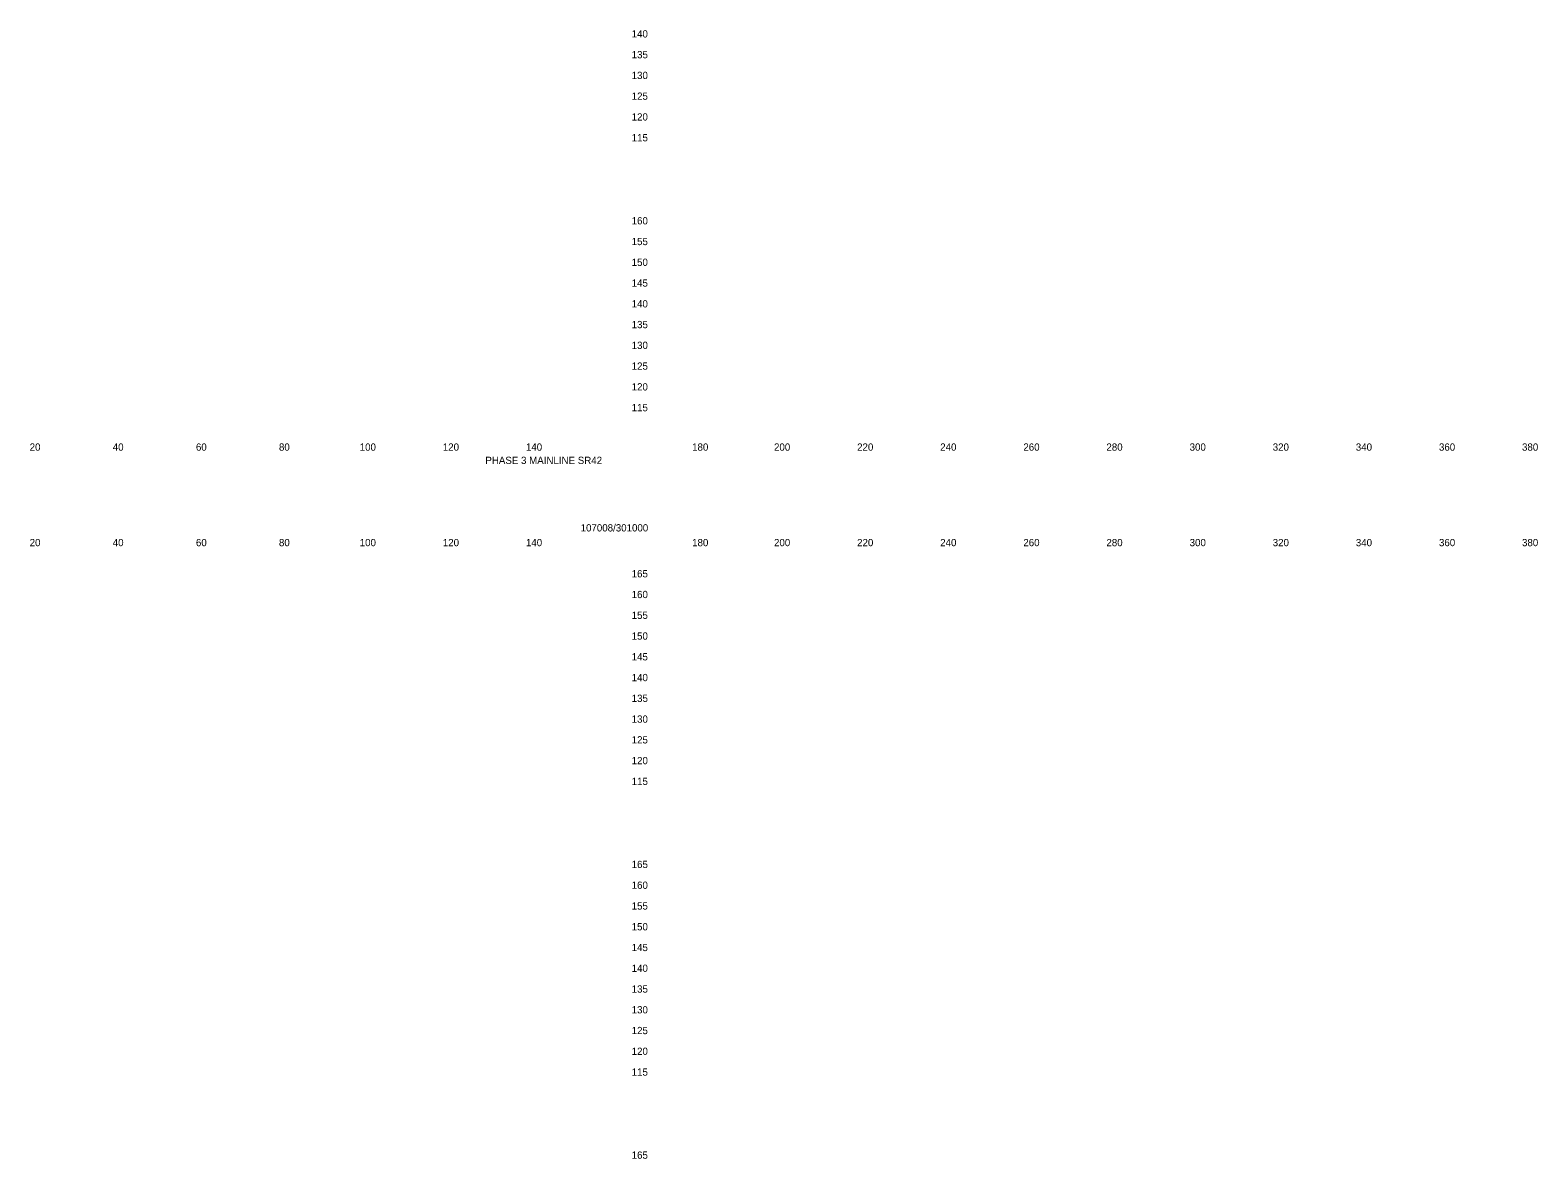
# Model space of a CAD drawing. Extents: x 21281 to 22024, y 6472 to 15198.
# Drawn here: x 21661.4 to 22024.2, y 8374.8 to 8646.6 of the extents above; entities that cross this region are included whole.
import ezdxf

# ---------------------------------------------------------------- set-up
doc = ezdxf.new("R2010")
doc.units = 0
doc.layers.add('Draft_XS_Grid', color=7, linetype='Continuous')
doc.layers.add('Draft_XS_Text', color=7, linetype='Continuous')

msp = doc.modelspace()

# ---------------------------------------------------------------- texts
at = {"layer": 'Draft_XS_Grid'}
for s, p in [('  140  ', (21804.84, 8644.84)), ('  135  ', (21804.84, 8639.84)), ('  130  ', (21804.84, 8634.84)), ('  125  ', (21804.84, 8629.84)), ('  120  ', (21804.84, 8624.84)), ('  115  ', (21804.84, 8619.84)), ('  160  ', (21804.84, 8599.84)), ('  155  ', (21804.84, 8594.84)), ('  150  ', (21804.84, 8589.84)), ('  145  ', (21804.84, 8584.84)), ('  140  ', (21804.84, 8579.84)), ('  135  ', (21804.84, 8574.84)), ('  130  ', (21804.84, 8569.84)), ('  125  ', (21804.84, 8564.84)), ('  120  ', (21804.84, 8559.84)), ('  115  ', (21804.84, 8554.84)), ('  165  ', (21804.84, 8514.84)), ('  160  ', (21804.84, 8509.84)), ('  155  ', (21804.84, 8504.84)), ('  150  ', (21804.84, 8499.84)), ('  145  ', (21804.84, 8494.84)), ('  140  ', (21804.84, 8489.84)), ('  135  ', (21804.84, 8484.84)), ('  130  ', (21804.84, 8479.84)), ('  125  ', (21804.84, 8474.84)), ('  120  ', (21804.84, 8469.84)), ('  115  ', (21804.84, 8464.84)), ('  165  ', (21804.84, 8444.84)), ('  160  ', (21804.84, 8439.84)), ('  155  ', (21804.84, 8434.84)), ('  150  ', (21804.84, 8429.84)), ('  145  ', (21804.84, 8424.84)), ('  140  ', (21804.84, 8419.84)), ('  135  ', (21804.84, 8414.84)), ('  130  ', (21804.84, 8409.84)), ('  125  ', (21804.84, 8404.84)), ('  120  ', (21804.84, 8399.84)), ('  115  ', (21804.84, 8394.84)), ('  165  ', (21804.84, 8374.84))]:
    msp.add_text(s, height=1.75, dxfattribs=at).set_placement(p)
at = {"layer": 'Draft_XS_Text'}
for s, p in [('  20  ', (21659.95, 8545.34)), ('  40  ', (21679.95, 8545.34)), ('  60  ', (21699.97, 8545.34)), ('  80  ', (21719.95, 8545.34)), ('  100  ', (21739.39, 8545.34)), ('  120  ', (21759.39, 8545.34)), ('  140  ', (21779.39, 8545.34)), ('  180  ', (21819.39, 8545.34)), ('  200  ', (21839.1, 8545.34)), ('  220  ', (21859.1, 8545.34)), ('  240  ', (21879.1, 8545.34)), ('  260  ', (21899.11, 8545.34)), ('  280  ', (21919.1, 8545.34)), ('  300  ', (21939.13, 8545.34)), ('  320  ', (21959.13, 8545.34)), ('  340  ', (21979.13, 8545.34)), ('  360  ', (21999.14, 8545.34)), ('  380  ', (22019.13, 8545.34)), ('PHASE 3 MAINLINE SR42', (21770.93, 8542.14)), ('107008/301000', (21793.86, 8525.89)), ('  20  ', (21659.95, 8522.34)), ('  40  ', (21679.95, 8522.34)), ('  60  ', (21699.97, 8522.34)), ('  80  ', (21719.95, 8522.34)), ('  100  ', (21739.39, 8522.34)), ('  120  ', (21759.39, 8522.34)), ('  140  ', (21779.39, 8522.34)), ('  180  ', (21819.39, 8522.34)), ('  200  ', (21839.1, 8522.34)), ('  220  ', (21859.1, 8522.34)), ('  240  ', (21879.1, 8522.34)), ('  260  ', (21899.11, 8522.34)), ('  280  ', (21919.1, 8522.34)), ('  300  ', (21939.13, 8522.34)), ('  320  ', (21959.13, 8522.34)), ('  340  ', (21979.13, 8522.34)), ('  360  ', (21999.14, 8522.34)), ('  380  ', (22019.13, 8522.34))]:
    msp.add_text(s, height=1.75, dxfattribs=at).set_placement(p)

doc.saveas('drawing.dxf')
